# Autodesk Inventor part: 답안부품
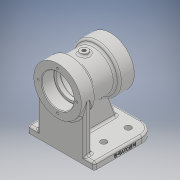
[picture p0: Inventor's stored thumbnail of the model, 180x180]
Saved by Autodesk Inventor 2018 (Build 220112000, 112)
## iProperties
Created: 2020-06
Part Number: 답안부품
Material: 일반
Document SubType Name: Modeling
Designer: USER
Density: 1 g/cm^3
Appearance: 기본값
Author: USER
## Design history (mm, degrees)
sketch "스케치1"
  geometry: L1 (-49, -45)-(49, -45); L2 (49, -45)-(49, 45); L3 (49, 45)-(-49, 45); L4 (-49, 45)-(-49, -45); L5 (-49, -45)-(49, 45); L6 (49, -45)-(-49, 45); 1 further point
  constraints: 12 end point, 2 midpoint, 2 parallel, 1 horizontal, 1 perpendicular
  dimensions: "d0" = 98 distance of L3.end L2.end; "d1" = 90 distance of L2.end L1.end
extrude "돌출1" new body sketch "스케치1" distance "d2" = 10; taper "d3" = 0 deg
sketch "스케치2"
  geometry: L1 (-50, 80)-(28, 80); L2 (-50, 80)-(-50, 115); L3 (-50, 115)-(-28, 115); L4 (-28, 115)-(-28, 109); L5 (-28, 109)-(6, 109); L6 (6, 109)-(6, 115); L7 (6, 115)-(28, 115); L8 (28, 115)-(28, 80); L9 (-45, 0)-(45, 0) reference; L10 (-45, 0)-(-45, 10) reference; 1 further point
  constraints: 16 end point, 5 perpendicular, 2 point on line, 1 horizontal, 1 vertical
  dimensions: "d4" = 78 distance of L1.start L1.end; "d5" = 70 diameter of L3 L1; "d6" = 80 distance between parallel lines of L9 L1; "d7" = 5 distance between parallel lines of L2 L10; "d8" = 22 distance of L2.end L3.end; "d9" = 22 distance of L6.end L7.end; "d10" = 58 diameter of L5 L1
revolve "회전1" sketch "스케치2" stored, may be unused: angle "d11" = 90 deg
sketch "스케치3"
  geometry: L1 (-35, -35)-(35, -35); L2 (35, -35)-(35, -45); L3 (35, -45)-(-35, -45); L4 (-35, -45)-(-35, -35); L5 (-49, -45)-(49, -45) reference; 2 further points
  constraints: 8 end point, 2 midpoint, 2 parallel, 1 horizontal, 1 perpendicular
  dimensions: "d12" = 70 distance of L2.end L3.end; "d13" = 10 distance of L1.end L2.end
hole "구멍1" diameter "d16" = 40; stored, may be unused: countersink angle "d20" = 90 deg, drill point angle "d22" = 0 deg; dims "d17" = 6, "d18" = 47, "d19" = 18, "d21" = 24, "d23" = 10, "d24" = 10
hole "구멍2" diameter "d27" = 46; stored, may be unused: countersink angle "d31" = 90 deg, drill point angle "d33" = 0 deg; dims "d25" = 10, "d26" = 10, "d28" = 6, "d29" = 47, "d30" = 18, "d32" = 30
extrude "돌출2" join sketch "스케치3" stored distance "d34" = 10; taper "d35" = 0 deg
sketch "스케치4" dims "d75" = 0.3
  geometry: L1 (45, 10)-(-45, 10) reference; L2 (6, 45)-(6, 115) reference; L3 (28, 45)-(28, 115) reference; L4 (6, 45)-(28, 45) reference; L5 (33, 10)-(20.261, 45); L6 (45, 0)-(45, 10) reference; 1 further point
  constraints: 2 end point, 2 point on line
  dimensions: "d36" = 70 deg angle of L1 L5; "d37" = 12 distance from line of L6 L5.start
feature "리브1" sketch "스케치4" dims "d38" = 1, "d39" = 10, "d40" = 0, "d41" = 0, "d42" = 1, "d43" = 1
sketch "스케치6" dims "d58" = 57
  geometry: C1 r 35 at (0, 0) reference; 3 further points
  constraints: 2 vertical alignment, 3 other
hole "구멍4" sketch "스케치6" at (0, 28.5) diameter "d59" = 3.242; stored, may be unused: countersink angle "d63" = 90 deg, drill point angle "d65" = 118 deg; dims "d60" = 10, "d61" = 47, "d62" = 18, "d64" = 12
node "작업 평면1"
node "작업 평면2"
sketch "스케치5"
  geometry: L1 (5, -28)-(-5, -28) reference; L2 (-5, -28)-(-5, 6) reference; L3 (5, 6)-(-5, 6) reference; L4 (5, 6)-(5, -28) reference; L5 (29, 6)-(-29, 6) reference; L6 (35, -28)-(-35, -28) reference; C1 r 6 at (0, -11); 1 further point
  constraints: 1 centre point, 1 vertical alignment
  dimensions: "d46" = 12 diameter of C1
extrude "돌출3" join sketch "스케치5" stored distance "d47" = 10; taper "d48" = 0 deg
hole "구멍3" diameter "d51" = 5.188; stored, may be unused: countersink angle "d55" = 90 deg, drill point angle "d57" = 0 deg; dims "d49" = 10, "d50" = 10, "d52" = 40, "d53" = 47, "d54" = 18, "d56" = 16
sketch "스케치7"
  geometry: L1 (-14.583, 29.907)-(-14.583, 60.093); L2 (-14.583, 60.093)-(6.583, 60.093); L3 (6.583, 60.093)-(6.583, 29.907); L4 (6.583, 29.907)-(-14.583, 29.907); L5 (-14.583, 45)-(6.583, 45); L6 (-4, 29.907)-(-4, 60.093); L7 (0, 0)-(-10, 0) reference; L8 (0, 0)-(0, 90) reference; 1 further point
  constraints: 4 end point, 4 midpoint, 2 other
  dimensions: "d69" = 45 distance between parallel lines of L5 L7; "d70" = 4 distance between parallel lines of L8 L6
feature "엠보싱1" sketch "스케치7" dims "d0" = 98, "d1" = 90, "d71" = 0.5, "d72" = 0
fillet "모깎기1" dims "d73" = 20
chamfer "모따기1" distance "d76" = 1; stored, may be unused: second distance "d77" = 2, angle "d78" = 45 deg
fillet "모깎기2" dims "d75" = 0.3
fillet "모깎기5" dims "d79" = 3
hole "구멍5" diameter "d82" = 9; stored, may be unused: countersink angle "d86" = 90 deg, drill point angle "d88" = 118 deg; dims "d80" = 10, "d81" = 10, "d83" = 10, "d84" = 47, "d85" = 18, "d87" = 12
node "솔리드1"
pattern_circular "원형 패턴1" dims angle "d67" = 360 deg
mirror "미러1"
fillet "모깎기3" dims "d74" = 3
pattern_linear "직사각형 패턴1" dims "d91" = 36, "d94" = 58
node "투영된 루프1"
node "투영된 루프2"
other parameters: "d44" = -39, "d45" = -112
